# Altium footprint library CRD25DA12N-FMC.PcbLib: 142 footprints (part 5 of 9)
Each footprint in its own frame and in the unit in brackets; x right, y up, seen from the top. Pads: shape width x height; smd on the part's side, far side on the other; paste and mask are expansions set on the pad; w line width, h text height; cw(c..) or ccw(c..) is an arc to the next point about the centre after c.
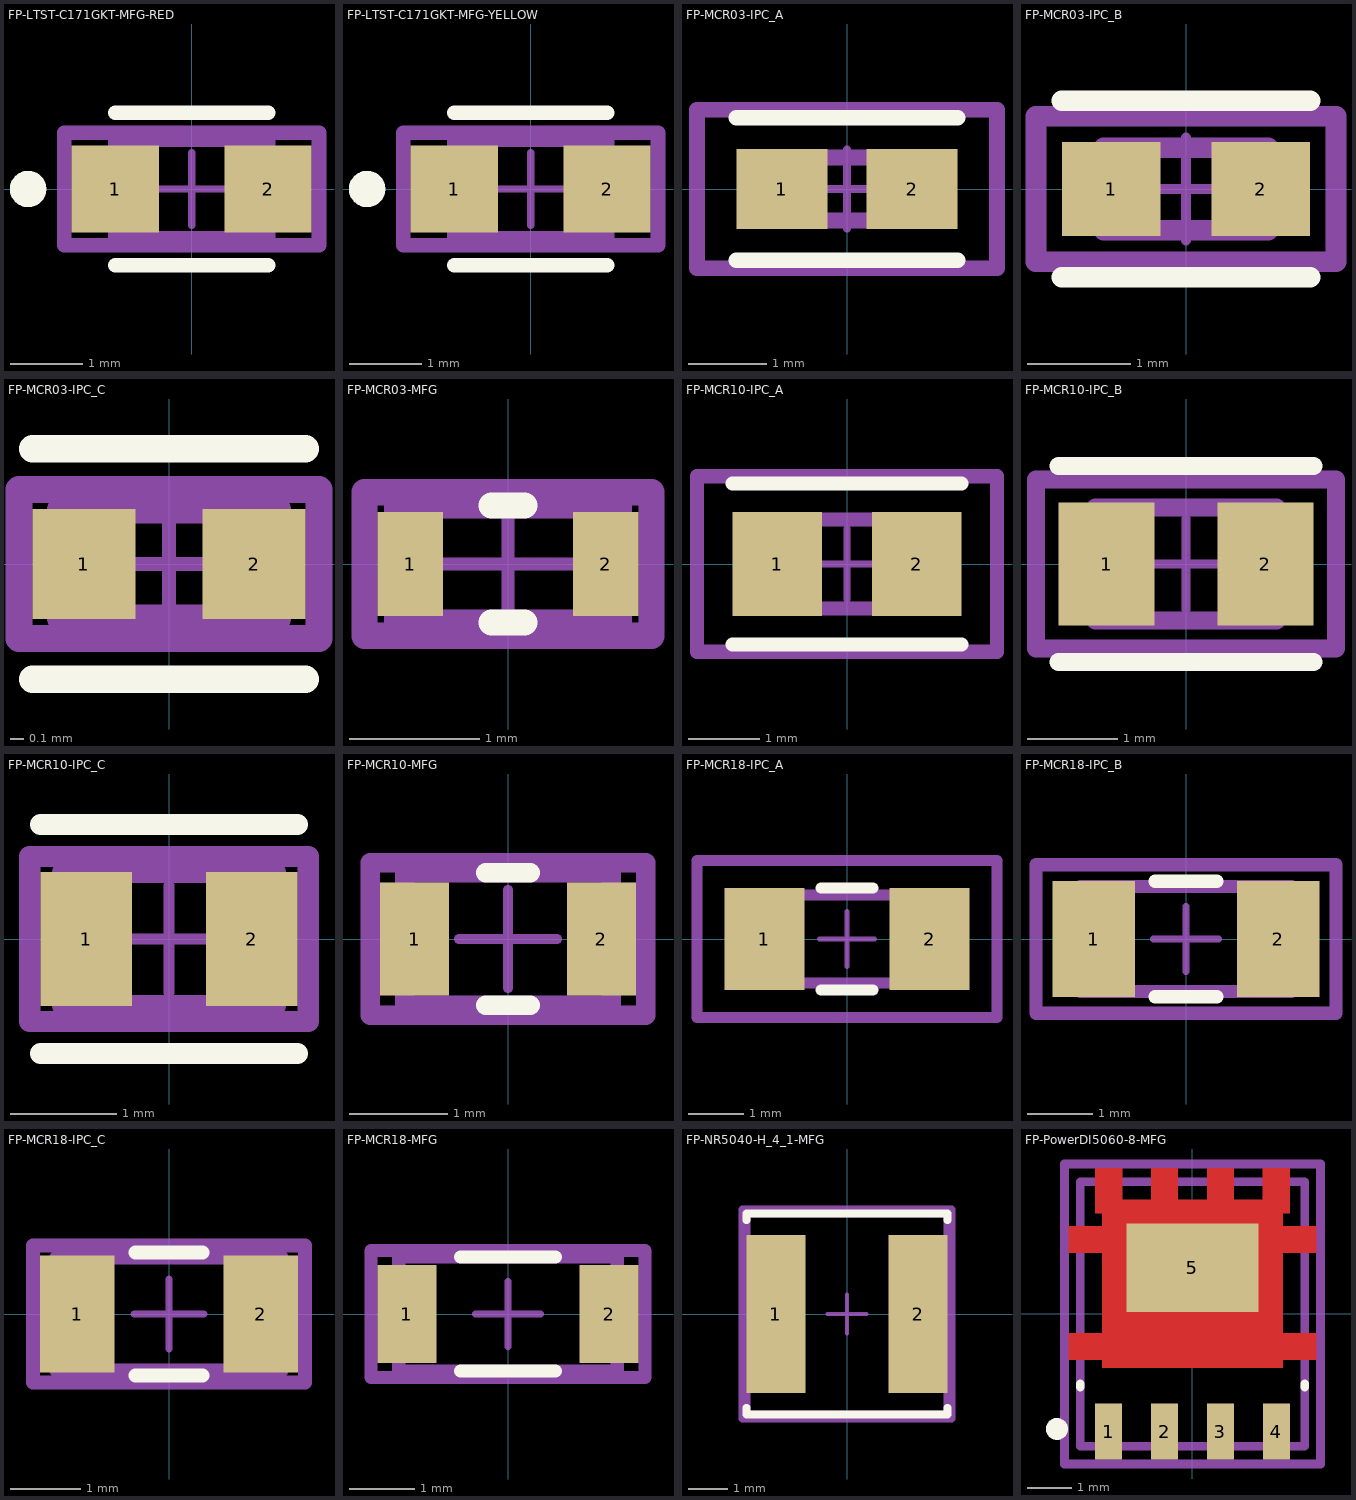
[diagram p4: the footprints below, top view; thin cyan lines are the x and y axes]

## FP-LTST-C171GKT-MFG-RED [mm]
pads (2):
  rect 1.2x1.2 smd paste+0 mask+0: 1(-1.05,0) 2(1.05,0)
Top Overlay:
  circle w0.25: c-2.25,0 r0.125
  lines w0.2: -1.05,-1.05 1.05,-1.05 ; -1.05,1.05 1.05,1.05
Mechanical 5:
  lines w0.2: -1.75,-0.775 -1.75,0.775 1.75,0.775 1.75,-0.775 -1.75,-0.775
  text ".Designator" at 0,0 h1
Mechanical 13:
  lines w0.2: -1.05,-0.675 -1.05,0.675 1.05,0.675 1.05,-0.675 -1.05,-0.675
Mechanical 15:
  lines w0.2: -1.75,-0.775 -1.75,0.775 1.75,0.775 1.75,-0.775 -1.75,-0.775
Mechanical 16:
  lines w0.1: -0.5,0 0.5,0 ; 0,-0.5 0,0.5
3D body "LED 0805 - RED.STEP": height 0.8, standoff 0, extent -1,-0.625 1,0.625

## FP-LTST-C171GKT-MFG-YELLOW [mm]
pads (2):
  rect 1.2x1.2 smd paste+0 mask+0: 1(-1.05,0) 2(1.05,0)
Top Overlay:
  circle w0.25: c-2.25,0 r0.125
  lines w0.2: -1.05,-1.05 1.05,-1.05 ; -1.05,1.05 1.05,1.05
Mechanical 5:
  lines w0.2: -1.75,-0.775 1.75,-0.775 1.75,0.775 -1.75,0.775 -1.75,-0.775
  text ".Designator" at 0,0 h1
Mechanical 13:
  lines w0.2: -1.05,-0.675 1.05,-0.675 1.05,0.675 -1.05,0.675 -1.05,-0.675
Mechanical 15:
  lines w0.2: -1.75,-0.775 1.75,-0.775 1.75,0.775 -1.75,0.775 -1.75,-0.775
Mechanical 16:
  lines w0.1: -0.5,0 0.5,0 ; 0,-0.5 0,0.5
3D body "LED 0805 - YELLOW.STEP": height 0.8, standoff 0, extent -1,-0.625 1,0.625

## FP-MCR03-IPC_A [mm]
pads (2):
  rect 1.158x1.012 smd paste+0 mask+0: 1(-0.827,0) 2(0.827,0)
Top Overlay:
  lines w0.2: -1.406,-0.906 1.406,-0.906 ; -1.406,0.906 1.406,0.906
Mechanical 5:
  lines w0.2: -1.906,-1.006 -1.906,1.006 1.906,1.006 1.906,-1.006 -1.906,-1.006
  text ".Designator" at 0,0.188 h1
Mechanical 13:
  lines w0.2: -0.8,-0.4 -0.8,0.4 0.8,0.4 0.8,-0.4 -0.8,-0.4
Mechanical 15:
  lines w0.2: -1.906,-1.006 -1.906,1.006 1.906,1.006 1.906,-1.006 -1.906,-1.006
Mechanical 16:
  lines w0.1: -0.5,0 0.5,0 ; 0,-0.5 0,0.5
3D body "Res_Rohm_MCR03ERTF1182_eec.STEP": height 0.25, standoff 0, extent -1.906,-1.006 1.906,1.006

## FP-MCR03-IPC_B [mm]
pads (2):
  rect 0.958x0.912 smd paste+0 mask+0: 1(-0.727,0) 2(0.727,0)
Top Overlay:
  lines w0.2: -1.206,-0.856 1.206,-0.856 ; -1.206,0.856 1.206,0.856
Mechanical 5:
  lines w0.2: -1.456,-0.706 1.456,-0.706 1.456,0.706 -1.456,0.706 -1.456,-0.706
  text ".Designator" at 0,0.188 h1
Mechanical 13:
  lines w0.2: -0.8,-0.4 0.8,-0.4 0.8,0.4 -0.8,0.4 -0.8,-0.4
Mechanical 15:
  lines w0.2: -1.456,-0.706 1.456,-0.706 1.456,0.706 -1.456,0.706 -1.456,-0.706
Mechanical 16:
  lines w0.1: -0.5,0 0.5,0 ; 0,-0.5 0,0.5
3D body "Res_Rohm_MCR03ERTF1182_eec.STEP": height 0.25, standoff 0, extent -1.456,-0.706 1.456,0.706

## FP-MCR03-IPC_C [mm]
pads (2):
  rect 0.758x0.812 smd paste+0 mask+0: 1(-0.627,0) 2(0.627,0)
Top Overlay:
  lines w0.2: -1.006,-0.85 1.006,-0.85 ; -1.006,0.85 1.006,0.85
Mechanical 5:
  lines w0.2: -1.106,-0.55 1.106,-0.55 1.106,0.55 -1.106,0.55 -1.106,-0.55
  text ".Designator" at 0,0.188 h1
Mechanical 13:
  lines w0.2: -0.8,-0.4 0.8,-0.4 0.8,0.4 -0.8,0.4 -0.8,-0.4
Mechanical 15:
  lines w0.2: -1.106,-0.55 1.106,-0.55 1.106,0.55 -1.106,0.55 -1.106,-0.55
Mechanical 16:
  lines w0.1: -0.5,0 0.5,0 ; 0,-0.5 0,0.5
3D body "Res_Rohm_MCR03ERTF1182_eec.STEP": height 0.25, standoff 0, extent -1.106,-0.55 1.106,0.55

## FP-MCR03-MFG [mm]
pads (2):
  rect 0.5x0.8 smd paste+0 mask+0: 1(-0.75,0) 2(0.75,0)
Top Overlay:
  lines w0.2: -0.125,-0.45 0.125,-0.45 ; -0.125,0.45 0.125,0.45
Mechanical 5:
  lines w0.2: -1.1,-0.55 -1.1,0.55 1.1,0.55 1.1,-0.55 -1.1,-0.55
  text ".Designator" at 0,0.188 h1
Mechanical 13:
  lines w0.2: -0.85,-0.45 -0.85,0.45 0.85,0.45 0.85,-0.45 -0.85,-0.45
Mechanical 15:
  lines w0.2: -1.1,-0.55 -1.1,0.55 1.1,0.55 1.1,-0.55 -1.1,-0.55
Mechanical 16:
  lines w0.1: -0.5,0 0.5,0 ; 0,-0.5 0,0.5
3D body "Res_Rohm_MCR03ERTF1182_eec.STEP": height 0.25, standoff 0, extent -1.1,-0.55 1.1,0.55

## FP-MCR10-IPC_A [mm]
pads (2):
  rect 1.258x1.462 smd paste+0 mask+0: 1(-0.977,0) 2(0.977,0)
Top Overlay:
  lines w0.2: -1.606,-1.131 1.606,-1.131 ; -1.606,1.131 1.606,1.131
Mechanical 5:
  lines w0.2: -2.106,-1.231 2.106,-1.231 2.106,1.231 -2.106,1.231 -2.106,-1.231
  text ".Designator" at 0,0.188 h1
Mechanical 13:
  lines w0.2: -1,-0.625 1,-0.625 1,0.625 -1,0.625 -1,-0.625
Mechanical 15:
  lines w0.2: -2.106,-1.231 2.106,-1.231 2.106,1.231 -2.106,1.231 -2.106,-1.231
Mechanical 16:
  lines w0.1: -0.5,0 0.5,0 ; 0,-0.5 0,0.5
3D body "Res_Rohm_MCR10ERTJ510_eec.STEP": height 0.25, standoff 0, extent -2.106,-1.231 2.106,1.231

## FP-MCR10-IPC_B [mm]
pads (2):
  rect 1.058x1.362 smd paste+0 mask+0: 1(-0.877,0) 2(0.877,0)
Top Overlay:
  lines w0.2: -1.406,-1.081 1.406,-1.081 ; -1.406,1.081 1.406,1.081
Mechanical 5:
  lines w0.2: -1.656,-0.931 1.656,-0.931 1.656,0.931 -1.656,0.931 -1.656,-0.931
  text ".Designator" at 0,0.188 h1
Mechanical 13:
  lines w0.2: -1,-0.625 1,-0.625 1,0.625 -1,0.625 -1,-0.625
Mechanical 15:
  lines w0.2: -1.656,-0.931 1.656,-0.931 1.656,0.931 -1.656,0.931 -1.656,-0.931
Mechanical 16:
  lines w0.1: -0.5,0 0.5,0 ; 0,-0.5 0,0.5
3D body "Res_Rohm_MCR10ERTJ510_eec.STEP": height 0.25, standoff 0, extent -1.656,-0.931 1.656,0.931

## FP-MCR10-IPC_C [mm]
pads (2):
  rect 0.858x1.262 smd paste+0 mask+0: 1(-0.777,0) 2(0.777,0)
Top Overlay:
  lines w0.2: -1.206,-1.075 1.206,-1.075 ; -1.206,1.075 1.206,1.075
Mechanical 5:
  lines w0.2: -1.306,-0.775 -1.306,0.775 1.306,0.775 1.306,-0.775 -1.306,-0.775
  text ".Designator" at 0,0.188 h1
Mechanical 13:
  lines w0.2: -1,-0.625 -1,0.625 1,0.625 1,-0.625 -1,-0.625
Mechanical 15:
  lines w0.2: -1.306,-0.775 -1.306,0.775 1.306,0.775 1.306,-0.775 -1.306,-0.775
Mechanical 16:
  lines w0.1: -0.5,0 0.5,0 ; 0,-0.5 0,0.5
3D body "Res_Rohm_MCR10ERTJ510_eec.STEP": height 0.25, standoff 0, extent -1.306,-0.775 1.306,0.775

## FP-MCR10-MFG [mm]
pads (2):
  rect 0.7x1.15 smd paste+0 mask+0: 1(-0.95,0) 2(0.95,0)
Top Overlay:
  lines w0.2: -0.225,-0.675 0.225,-0.675 ; -0.225,0.675 0.225,0.675
Mechanical 5:
  lines w0.2: -1.4,-0.775 -1.4,0.775 1.4,0.775 1.4,-0.775 -1.4,-0.775
  text ".Designator" at 0,0.188 h1
Mechanical 13:
  lines w0.2: -1.05,-0.675 -1.05,0.675 1.05,0.675 1.05,-0.675 -1.05,-0.675
Mechanical 15:
  lines w0.2: -1.4,-0.775 -1.4,0.775 1.4,0.775 1.4,-0.775 -1.4,-0.775
Mechanical 16:
  lines w0.1: -0.5,0 0.5,0 ; 0,-0.5 0,0.5
3D body "Res_Rohm_MCR10ERTJ510_eec.STEP": height 0.25, standoff 0, extent -1.4,-0.775 1.4,0.775

## FP-MCR18-IPC_A [mm]
pads (2):
  rect 1.456x1.858 smd paste+0 mask+0: 1(-1.501,0) 2(1.501,0)
Top Overlay:
  lines w0.2: -0.473,-0.929 0.473,-0.929 ; -0.473,0.929 0.473,0.929
Mechanical 5:
  lines w0.2: -2.729,-1.429 -2.729,1.429 2.729,1.429 2.729,-1.429 -2.729,-1.429
  text ".Designator" at 0,0.188 h1
Mechanical 13:
  lines w0.2: -1.6,-0.8 -1.6,0.8 1.6,0.8 1.6,-0.8 -1.6,-0.8
Mechanical 15:
  lines w0.2: -2.729,-1.429 -2.729,1.429 2.729,1.429 2.729,-1.429 -2.729,-1.429
Mechanical 16:
  lines w0.1: -0.5,0 0.5,0 ; 0,-0.5 0,0.5
3D body "Res_Rohm_MCR18ERTFL1R10_eec.STEP": height 0.25, standoff 0, extent -2.729,-1.429 2.729,1.429

## FP-MCR18-IPC_B [mm]
pads (2):
  rect 1.256x1.758 smd paste+0 mask+0: 1(-1.401,0) 2(1.401,0)
Top Overlay:
  lines w0.2: -0.473,-0.879 0.473,-0.879 ; -0.473,0.879 0.473,0.879
Mechanical 5:
  lines w0.2: -2.279,-1.129 -2.279,1.129 2.279,1.129 2.279,-1.129 -2.279,-1.129
  text ".Designator" at 0,0.188 h1
Mechanical 13:
  lines w0.2: -1.6,-0.8 -1.6,0.8 1.6,0.8 1.6,-0.8 -1.6,-0.8
Mechanical 15:
  lines w0.2: -2.279,-1.129 -2.279,1.129 2.279,1.129 2.279,-1.129 -2.279,-1.129
Mechanical 16:
  lines w0.1: -0.5,0 0.5,0 ; 0,-0.5 0,0.5
3D body "Res_Rohm_MCR18ERTFL1R10_eec.STEP": height 0.25, standoff 0, extent -2.279,-1.129 2.279,1.129

## FP-MCR18-IPC_C [mm]
pads (2):
  rect 1.056x1.658 smd paste+0 mask+0: 1(-1.301,0) 2(1.301,0)
Top Overlay:
  lines w0.2: -0.473,-0.875 0.473,-0.875 ; -0.473,0.875 0.473,0.875
Mechanical 5:
  lines w0.2: -1.929,-0.975 1.929,-0.975 1.929,0.975 -1.929,0.975 -1.929,-0.975
  text ".Designator" at 0,0.188 h1
Mechanical 13:
  lines w0.2: -1.6,-0.8 1.6,-0.8 1.6,0.8 -1.6,0.8 -1.6,-0.8
Mechanical 15:
  lines w0.2: -1.929,-0.975 1.929,-0.975 1.929,0.975 -1.929,0.975 -1.929,-0.975
Mechanical 16:
  lines w0.1: -0.5,0 0.5,0 ; 0,-0.5 0,0.5
3D body "Res_Rohm_MCR18ERTFL1R10_eec.STEP": height 0.25, standoff 0, extent -1.929,-0.975 1.929,0.975

## FP-MCR18-MFG [mm]
pads (2):
  rect 0.9x1.5 smd paste+0 mask+0: 1(-1.55,0) 2(1.55,0)
Top Overlay:
  lines w0.2: -0.725,-0.875 0.725,-0.875 ; -0.725,0.875 0.725,0.875
Mechanical 5:
  lines w0.2: -2.1,-0.975 -2.1,0.975 2.1,0.975 2.1,-0.975 -2.1,-0.975
  text ".Designator" at 0,0.188 h1
Mechanical 13:
  lines w0.2: -1.675,-0.875 -1.675,0.875 1.675,0.875 1.675,-0.875 -1.675,-0.875
Mechanical 15:
  lines w0.2: -2.1,-0.975 -2.1,0.975 2.1,0.975 2.1,-0.975 -2.1,-0.975
Mechanical 16:
  lines w0.1: -0.5,0 0.5,0 ; 0,-0.5 0,0.5
3D body "Res_Rohm_MCR18ERTFL1R10_eec.STEP": height 0.25, standoff 0, extent -2.1,-0.975 2.1,0.975

## FP-NR5040-H_4_1-MFG [mm]
pads (2):
  rect 1.5x4 smd paste+0 mask+0: 1(-1.8,0) 2(1.8,0)
Top Overlay:
  lines w0.2: -2.55,-2.375 -2.55,-2.55 2.55,-2.55 2.55,-2.375 ; -2.55,2.375 -2.55,2.55 2.55,2.55 2.55,2.375
Mechanical 5:
  lines w0.2: -2.65,-2.65 -2.65,2.65 2.65,2.65 2.65,-2.65 -2.65,-2.65
  text ".Designator" at 0,0.188 h1
Mechanical 13:
  lines w0.2: -2.55,-2.55 -2.55,2.55 2.55,2.55 2.55,-2.55 -2.55,-2.55
Mechanical 15:
  lines w0.2: -2.65,-2.65 -2.65,2.65 2.65,2.65 2.65,-2.65 -2.65,-2.65
Mechanical 16:
  lines w0.1: -0.5,0 0.5,0 ; 0,-0.5 0,0.5
3D body "Ind_Taiyo_Yuden_NR5040T1R5N_eec.STEP": height 0.25, standoff 0, extent -2.65,-2.65 2.65,2.65

## FP-PowerDI5060-8-MFG [mm]
pads (5):
  rect 0.61x1.27 smd paste+0 mask+0: 1(-1.905,-2.67) 2(-0.635,-2.67) 3(0.635,-2.67) 4(1.905,-2.67)
  rect 3x2 smd paste+0 mask+0: 5(0,1.05)
Top Layer:
  region: 2.05,-1.215 -2.05,-1.215 -2.05,-1.035 -2.805,-1.035 -2.805,-0.435 -2.05,-0.435 -2.05,1.39 -2.805,1.39 -2.805,1.99 -2.05,1.99 -2.05,2.285 -2.21,2.285 -2.21,3.305 -1.6,3.305 -1.6,2.595 -0.94,2.595 -0.94,3.305 -0.33,3.305 -0.33,2.595 0.33,2.595 0.33,3.305 0.94,3.305 0.94,2.595 1.6,2.595 1.6,3.305 2.21,3.305 2.21,2.285 2.05,2.285 2.05,1.99 2.805,1.99 2.805,1.39 2.05,1.39 2.05,-0.435 2.805,-0.435 2.805,-1.035 2.05,-1.035
Top Overlay:
  circle w0.25: c-3.075,-2.61 r0.125
  lines w0.2: -2.55,-1.66 -2.55,-1.59 ; 2.55,-1.66 2.55,-1.59
Mechanical 5:
  lines w0.2: -2.905,-3.405 2.905,-3.405 2.905,3.405 -2.905,3.405 -2.905,-3.405
  text ".Designator" at 0,0.188 h1
Mechanical 13:
  lines w0.2: -2.55,-3 2.55,-3 2.55,3 -2.55,3 -2.55,-3
Mechanical 15:
  lines w0.2: -2.905,-3.405 2.905,-3.405 2.905,3.405 -2.905,3.405 -2.905,-3.405
Mechanical 16:
  lines w0.1: -0.5,0 0.5,0 ; 0,-0.5 0,0.5
3D body "Trans_Diodes_DMT12H007LPS-13_eec.STEP": height 0.25, standoff 0, extent -2.905,-3.405 2.905,3.405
